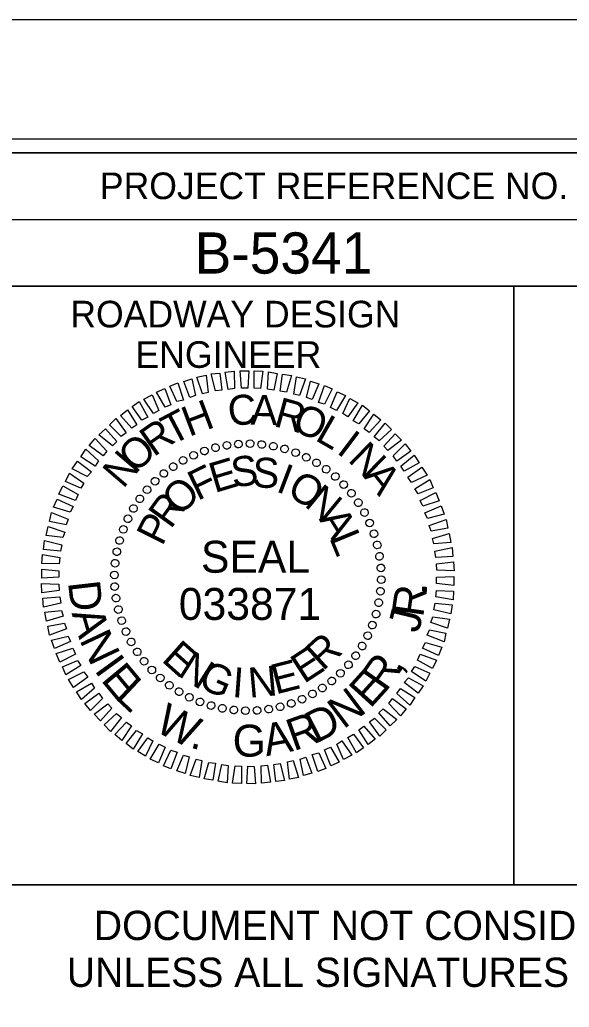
# Model space of a CAD drawing. Extents: x 572694 to 574378, y -52955 to -51855.
# Drawn here: x 574168.6 to 574271.9, y -52040.7 to -51855.1 of the extents above; entities that cross this region are included whole.
import ezdxf

# ---------------------------------------------------------------- set-up
doc = ezdxf.new("R2010")
doc.units = 0
for name, color, linetype in [('Sheet Cutting Line CELL', 7, 'Continuous'), ('Sheet Data Field CELL', 7, 'Continuous'), ('Sheet Plot Border Inside CELL', 7, 'Continuous'), ('Sheet Plot Border Outside CELL', 7, 'Continuous'), ('Sheet Professional Seal CELL', 7, 'Continuous'), ('Sheet Profile CELL', 7, 'Continuous'), ('Sheet Profile Grid Major CELL', 7, 'Continuous'), ('Sheet Sticker Exception Certification CELL', 7, 'Continuous')]:
    doc.layers.add(name, color=color, linetype=linetype)

msp = doc.modelspace()

# ---------------------------------------------------------------- linework, layer by layer
at = {"layer": 'Sheet Cutting Line CELL'}
msp.add_line((574378.5, -51855.14), (572694.5, -51855.14), dxfattribs=at)
at = {"layer": 'Sheet Plot Border Inside CELL'}
msp.add_lwpolyline([(574374, -51877.59), (572707.5, -51877.59), (572707.5, -52932.69), (574374, -52932.69)], close=True, dxfattribs=at)
at = {"layer": 'Sheet Plot Border Outside CELL'}
msp.add_lwpolyline([(574378.5, -51855.14), (572694.5, -51855.14), (572694.5, -52955.14), (574378.5, -52955.14)], close=True, dxfattribs=at)
at = {"layer": 'Sheet Professional Seal CELL'}
for p, q in [((574205.36, -51935.53), (574205.36, -51935.53)), ((574207.56, -51935.13), (574207.56, -51935.13)), ((574209.71, -51934.83), (574209.71, -51934.83)), ((574211.91, -51934.78), (574211.91, -51934.78)), ((574214.11, -51934.93), (574214.11, -51934.93)), ((574216.26, -51935.28), (574216.26, -51935.28)), ((574218.36, -51935.73), (574218.36, -51935.73)), ((574201.26, -51936.93), (574201.26, -51936.93)), ((574203.26, -51936.13), (574203.26, -51936.13)), ((574220.46, -51936.43), (574220.46, -51936.43)), ((574222.46, -51937.33), (574222.46, -51937.33)), ((574197.41, -51939.08), (574197.41, -51939.08)), ((574199.31, -51937.93), (574199.31, -51937.93)), ((574224.41, -51938.33), (574224.41, -51938.33)), ((574195.66, -51940.33), (574195.66, -51940.33)), ((574226.21, -51939.58), (574226.21, -51939.58)), ((574227.96, -51940.93), (574227.96, -51940.93)), ((574194.01, -51941.83), (574194.01, -51941.83)), ((574229.51, -51942.43), (574229.51, -51942.43)), ((574191.16, -51945.13), (574191.16, -51945.13)), ((574192.51, -51943.38), (574192.51, -51943.38)), ((574231.01, -51944.08), (574231.01, -51944.08)), ((574189.91, -51946.93), (574189.91, -51946.93)), ((574232.26, -51945.83), (574232.26, -51945.83)), ((574233.41, -51947.73), (574233.41, -51947.73)), ((574188.91, -51948.88), (574188.91, -51948.88)), ((574234.41, -51949.68), (574234.41, -51949.68)), ((574188.01, -51950.88), (574188.01, -51950.88)), ((574235.21, -51951.68), (574235.21, -51951.68)), ((574187.31, -51952.98), (574187.31, -51952.98)), ((574235.81, -51953.78), (574235.81, -51953.78)), ((574186.86, -51955.08), (574186.86, -51955.08)), ((574236.21, -51955.98), (574236.21, -51955.98)), ((574186.51, -51957.23), (574186.51, -51957.23)), ((574236.51, -51958.13), (574236.51, -51958.13)), ((574186.36, -51959.43), (574186.36, -51959.43)), ((574211.46, -51959.88), (574211.46, -51959.88)), ((574186.41, -51961.63), (574186.41, -51961.63)), ((574236.56, -51960.33), (574236.56, -51960.33)), ((574236.41, -51962.53), (574236.41, -51962.53)), ((574186.71, -51963.78), (574186.71, -51963.78)), ((574236.06, -51964.68), (574236.06, -51964.68)), ((574187.11, -51965.98), (574187.11, -51965.98)), ((574235.61, -51966.78), (574235.61, -51966.78)), ((574187.71, -51968.08), (574187.71, -51968.08)), ((574234.91, -51968.88), (574234.91, -51968.88)), ((574188.51, -51970.08), (574188.51, -51970.08)), ((574234.01, -51970.88), (574234.01, -51970.88)), ((574189.51, -51972.03), (574189.51, -51972.03)), ((574233.01, -51972.83), (574233.01, -51972.83)), ((574190.66, -51973.93), (574190.66, -51973.93)), ((574231.76, -51974.63), (574231.76, -51974.63)), ((574191.91, -51975.68), (574191.91, -51975.68)), ((574230.41, -51976.38), (574230.41, -51976.38)), ((574193.41, -51977.33), (574193.41, -51977.33)), ((574228.91, -51977.93), (574228.91, -51977.93)), ((574194.96, -51978.83), (574194.96, -51978.83)), ((574196.71, -51980.18), (574196.71, -51980.18)), ((574227.26, -51979.43), (574227.26, -51979.43)), ((574198.51, -51981.43), (574198.51, -51981.43)), ((574223.61, -51981.83), (574223.61, -51981.83)), ((574225.51, -51980.68), (574225.51, -51980.68)), ((574200.46, -51982.43), (574200.46, -51982.43)), ((574202.46, -51983.33), (574202.46, -51983.33)), ((574204.56, -51984.03), (574204.56, -51984.03)), ((574219.66, -51983.63), (574219.66, -51983.63)), ((574221.66, -51982.83), (574221.66, -51982.83)), ((574206.66, -51984.48), (574206.66, -51984.48)), ((574208.81, -51984.83), (574208.81, -51984.83)), ((574211.01, -51984.98), (574211.01, -51984.98)), ((574213.21, -51984.93), (574213.21, -51984.93)), ((574215.36, -51984.63), (574215.36, -51984.63)), ((574217.56, -51984.23), (574217.56, -51984.23))]:
    msp.add_line(p, q, dxfattribs=at)
for points in [[(574200.56, -51926.08), (574199.41, -51923.08), (574200.96, -51922.63), (574201.61, -51925.73)], [(574202.96, -51925.43), (574201.91, -51922.28), (574203.61, -51921.93), (574204.01, -51925.18)], [(574205.36, -51924.88), (574204.56, -51921.68), (574206.21, -51921.53), (574206.56, -51924.73)], [(574207.76, -51924.58), (574207.21, -51921.38), (574208.91, -51921.18), (574208.96, -51924.43)], [(574210.26, -51924.33), (574210.01, -51921.08), (574211.66, -51921.13), (574211.46, -51924.38)], [(574212.66, -51924.38), (574212.66, -51921.13), (574214.31, -51921.18), (574213.86, -51924.43)], [(574215.16, -51924.53), (574215.36, -51921.28), (574217.01, -51921.58), (574216.36, -51924.73)], [(574217.56, -51924.93), (574218.01, -51921.73), (574219.66, -51921.98), (574218.76, -51925.08)], [(574220.11, -51925.48), (574220.61, -51922.23), (574222.31, -51922.63), (574221.16, -51925.73)], [(574195.91, -51927.93), (574194.31, -51925.13), (574195.86, -51924.43), (574197.01, -51927.48)], [(574198.11, -51926.88), (574196.81, -51923.98), (574198.31, -51923.38), (574199.36, -51926.58)], [(574222.51, -51926.13), (574223.26, -51923.03), (574224.81, -51923.53), (574223.56, -51926.48)], [(574224.76, -51927.03), (574225.91, -51923.88), (574227.31, -51924.48), (574225.91, -51927.38)], [(574193.76, -51929.13), (574191.91, -51926.43), (574193.46, -51925.63), (574194.71, -51928.53)], [(574227.01, -51927.98), (574228.26, -51925.03), (574229.81, -51925.73), (574228.11, -51928.53)], [(574229.31, -51929.13), (574230.66, -51926.28), (574232.16, -51927.13), (574230.26, -51929.73)], [(574189.66, -51931.88), (574187.51, -51929.48), (574188.86, -51928.43), (574190.61, -51931.23)], [(574191.56, -51930.38), (574189.71, -51927.83), (574191.01, -51926.88), (574192.66, -51929.78)], [(574231.26, -51930.48), (574233.01, -51927.58), (574234.31, -51928.63), (574232.36, -51931.08)], [(574187.66, -51933.43), (574185.46, -51931.23), (574186.66, -51930.03), (574188.61, -51932.73)], [(574233.31, -51931.98), (574235.16, -51929.23), (574236.46, -51930.33), (574234.26, -51932.68)], [(574186.01, -51935.18), (574183.46, -51933.13), (574184.71, -51931.98), (574186.81, -51934.38)], [(574235.21, -51933.53), (574237.26, -51930.93), (574238.46, -51932.13), (574236.16, -51934.28)], [(574184.26, -51937.08), (574181.66, -51935.13), (574182.76, -51933.83), (574184.96, -51936.18)], [(574237.01, -51935.28), (574239.16, -51932.93), (574240.36, -51934.13), (574237.76, -51936.08)], [(574182.76, -51938.98), (574180.06, -51937.28), (574181.01, -51935.83), (574183.41, -51938.03)], [(574238.76, -51937.08), (574241.06, -51934.83), (574242.11, -51936.18), (574239.46, -51938.08)], [(574240.26, -51939.03), (574242.71, -51936.93), (574243.66, -51938.38), (574240.86, -51939.98)], [(574181.26, -51940.98), (574178.46, -51939.48), (574179.46, -51938.08), (574182.06, -51940.08)], [(574241.56, -51941.08), (574244.21, -51939.18), (574245.16, -51940.68), (574242.26, -51942.08)], [(574180.06, -51943.13), (574177.21, -51941.88), (574177.96, -51940.33), (574180.66, -51942.18)], [(574179.06, -51945.43), (574175.96, -51944.28), (574176.71, -51942.73), (574179.56, -51944.33)], [(574242.86, -51943.28), (574245.66, -51941.53), (574246.31, -51943.08), (574243.46, -51944.23)], [(574243.86, -51945.43), (574246.81, -51943.93), (574247.46, -51945.53), (574244.36, -51946.53)], [(574178.06, -51947.63), (574174.96, -51946.73), (574175.61, -51945.18), (574178.61, -51946.58)], [(574244.76, -51947.78), (574247.81, -51946.48), (574248.36, -51948.03), (574245.26, -51948.83)], [(574177.31, -51950.03), (574174.21, -51949.38), (574174.56, -51947.73), (574177.71, -51948.98)], [(574176.66, -51952.43), (574173.56, -51952.03), (574173.91, -51950.33), (574177.06, -51951.38)], [(574245.56, -51950.18), (574248.76, -51949.03), (574249.06, -51950.68), (574245.91, -51951.23)], [(574246.16, -51952.58), (574249.31, -51951.63), (574249.61, -51953.33), (574246.46, -51953.63)], [(574176.26, -51954.98), (574173.06, -51954.68), (574173.26, -51952.98), (574176.51, -51953.78)], [(574246.61, -51954.98), (574249.86, -51954.28), (574250.01, -51955.98), (574246.81, -51956.18)], [(574176.01, -51957.38), (574172.76, -51957.28), (574172.86, -51955.63), (574176.11, -51956.18)], [(574246.91, -51957.38), (574250.16, -51956.98), (574250.26, -51958.68), (574247.01, -51958.58)], [(574175.96, -51959.88), (574172.71, -51960.03), (574172.71, -51958.33), (574175.96, -51958.68)], [(574246.96, -51959.88), (574250.21, -51959.73), (574250.21, -51961.43), (574246.96, -51961.08)], [(574176.01, -51962.38), (574172.76, -51962.78), (574172.66, -51961.08), (574175.91, -51961.18)], [(574176.31, -51964.78), (574173.06, -51965.48), (574172.91, -51963.78), (574176.11, -51963.58)], [(574246.91, -51962.38), (574250.16, -51962.48), (574250.06, -51964.13), (574246.81, -51963.58)], [(574246.66, -51964.78), (574249.86, -51965.08), (574249.66, -51966.78), (574246.41, -51965.98)], [(574176.76, -51967.18), (574173.61, -51968.13), (574173.31, -51966.43), (574176.46, -51966.13)], [(574246.26, -51967.33), (574249.36, -51967.73), (574249.01, -51969.43), (574245.86, -51968.38)], [(574177.36, -51969.58), (574174.16, -51970.73), (574173.86, -51969.08), (574177.01, -51968.53)], [(574178.16, -51971.98), (574175.11, -51973.28), (574174.56, -51971.73), (574177.66, -51970.93)], [(574245.61, -51969.73), (574248.71, -51970.38), (574248.36, -51972.03), (574245.21, -51970.78)], [(574244.86, -51972.13), (574247.96, -51973.03), (574247.31, -51974.58), (574244.31, -51973.18)], [(574179.06, -51974.33), (574176.11, -51975.83), (574175.46, -51974.23), (574178.56, -51973.23)], [(574243.86, -51974.33), (574246.96, -51975.48), (574246.21, -51977.03), (574243.36, -51975.43)], [(574180.06, -51976.48), (574177.26, -51978.23), (574176.61, -51976.68), (574179.46, -51975.53)], [(574242.86, -51976.63), (574245.71, -51977.88), (574244.96, -51979.43), (574242.26, -51977.58)], [(574181.36, -51978.68), (574178.71, -51980.58), (574177.76, -51979.08), (574180.66, -51977.68)], [(574182.66, -51980.73), (574180.21, -51982.83), (574179.26, -51981.38), (574182.06, -51979.78)], [(574241.66, -51978.78), (574244.46, -51980.28), (574243.46, -51981.68), (574240.86, -51979.68)], [(574184.16, -51982.68), (574181.86, -51984.93), (574180.81, -51983.58), (574183.46, -51981.68)], [(574240.16, -51980.78), (574242.86, -51982.48), (574241.91, -51983.93), (574239.51, -51981.73)], [(574185.91, -51984.48), (574183.76, -51986.83), (574182.56, -51985.63), (574185.16, -51983.68)], [(574238.66, -51982.68), (574241.26, -51984.63), (574240.16, -51985.93), (574237.96, -51983.58)], [(574187.71, -51986.23), (574185.66, -51988.83), (574184.46, -51987.63), (574186.76, -51985.48)], [(574236.91, -51984.58), (574239.46, -51986.63), (574238.21, -51987.78), (574236.11, -51985.38)], [(574189.61, -51987.78), (574187.76, -51990.53), (574186.46, -51989.43), (574188.66, -51987.08)], [(574235.26, -51986.33), (574237.46, -51988.53), (574236.26, -51989.73), (574234.31, -51987.03)], [(574191.66, -51989.28), (574189.91, -51992.18), (574188.61, -51991.13), (574190.56, -51988.68)], [(574231.36, -51989.38), (574233.21, -51991.93), (574231.91, -51992.88), (574230.26, -51989.98)], [(574233.26, -51987.88), (574235.41, -51990.28), (574234.06, -51991.33), (574232.31, -51988.53)], [(574193.61, -51990.63), (574192.26, -51993.48), (574190.76, -51992.63), (574192.66, -51990.03)], [(574195.91, -51991.78), (574194.66, -51994.73), (574193.11, -51994.03), (574194.81, -51991.23)], [(574229.16, -51990.63), (574231.01, -51993.33), (574229.46, -51994.13), (574228.21, -51991.23)], [(574198.16, -51992.73), (574197.01, -51995.88), (574195.61, -51995.28), (574197.01, -51992.38)], [(574200.41, -51993.63), (574199.66, -51996.73), (574198.11, -51996.23), (574199.36, -51993.28)], [(574224.81, -51992.88), (574226.11, -51995.78), (574224.61, -51996.38), (574223.56, -51993.18)], [(574227.01, -51991.83), (574228.61, -51994.63), (574227.06, -51995.33), (574225.91, -51992.28)], [(574202.81, -51994.28), (574202.31, -51997.53), (574200.61, -51997.13), (574201.76, -51994.03)], [(574205.36, -51994.83), (574204.91, -51998.03), (574203.26, -51997.78), (574204.16, -51994.68)], [(574207.76, -51995.23), (574207.56, -51998.48), (574205.91, -51998.18), (574206.56, -51995.03)], [(574215.16, -51995.18), (574215.71, -51998.38), (574214.01, -51998.58), (574213.96, -51995.33)], [(574217.56, -51994.88), (574218.36, -51998.08), (574216.71, -51998.23), (574216.36, -51995.03)], [(574219.96, -51994.33), (574221.01, -51997.48), (574219.31, -51997.83), (574218.91, -51994.58)], [(574222.36, -51993.68), (574223.51, -51996.68), (574221.96, -51997.13), (574221.31, -51994.03)], [(574210.26, -51995.38), (574210.26, -51998.63), (574208.61, -51998.58), (574209.06, -51995.33)], [(574212.66, -51995.43), (574212.91, -51998.68), (574211.26, -51998.63), (574211.46, -51995.38)]]:
    msp.add_lwpolyline(points, close=True, dxfattribs=at)
for centre, major_axis in [((574203.3, -51936.17), (-0.234, 0.681)), ((574205.39, -51935.54), (-0.174, 0.699)), ((574207.54, -51935.11), (-0.113, 0.711)), ((574209.71, -51934.86), (-0.05, 0.718)), ((574211.9, -51934.8), (0.013, 0.72)), ((574214.08, -51934.94), (0.075, 0.716)), ((574216.25, -51935.26), (0.137, 0.707)), ((574218.37, -51935.77), (0.198, 0.692)), ((574220.45, -51936.47), (0.258, 0.672)), ((574199.3, -51937.94), (-0.349, 0.63)), ((574201.26, -51936.97), (-0.293, 0.658)), ((574222.46, -51937.34), (0.316, 0.647)), ((574224.38, -51938.38), (0.371, 0.617)), ((574195.68, -51940.39), (-0.453, 0.56)), ((574197.44, -51939.09), (-0.403, 0.597)), ((574226.2, -51939.59), (0.423, 0.582)), ((574194.04, -51941.84), (-0.5, 0.518)), ((574227.92, -51940.95), (0.472, 0.543)), ((574192.53, -51943.43), (-0.543, 0.472)), ((574229.5, -51942.46), (0.518, 0.5)), ((574230.95, -51944.1), (0.56, 0.453)), ((574191.17, -51945.14), (-0.582, 0.423)), ((574232.25, -51945.85), (0.597, 0.403)), ((574189.96, -51946.96), (-0.617, 0.371)), ((574233.4, -51947.72), (0.63, 0.349)), ((574188.92, -51948.89), (-0.647, 0.316)), ((574188.05, -51950.89), (-0.672, 0.258)), ((574234.37, -51949.68), (0.658, 0.293)), ((574187.35, -51952.97), (-0.692, 0.198)), ((574235.18, -51951.71), (0.681, 0.234)), ((574186.84, -51955.09), (-0.707, 0.137)), ((574235.8, -51953.81), (0.699, 0.174)), ((574236.23, -51955.96), (0.711, 0.113)), ((574186.52, -51957.26), (-0.716, 0.075)), ((574236.48, -51958.13), (0.718, 0.05)), ((574186.39, -51959.44), (-0.72, 0.013)), ((574236.54, -51960.32), (0.72, -0.013)), ((574186.44, -51961.63), (-0.718, -0.05)), ((574236.4, -51962.5), (0.716, -0.075)), ((574186.69, -51963.8), (-0.711, -0.113)), ((574187.13, -51965.95), (-0.699, -0.174)), ((574236.08, -51964.66), (0.707, -0.137)), ((574187.75, -51968.04), (-0.681, -0.234)), ((574235.57, -51966.79), (0.692, -0.198)), ((574188.55, -51970.08), (-0.658, -0.293)), ((574234.88, -51968.87), (0.672, -0.258)), ((574234, -51970.87), (0.647, -0.316)), ((574189.53, -51972.04), (-0.63, -0.349)), ((574232.96, -51972.8), (0.617, -0.371)), ((574190.67, -51973.9), (-0.597, -0.403)), ((574231.75, -51974.62), (0.582, -0.423)), ((574191.97, -51975.66), (-0.56, -0.453)), ((574193.42, -51977.3), (-0.518, -0.5)), ((574230.39, -51976.33), (0.543, -0.472)), ((574195.01, -51978.81), (-0.472, -0.543)), ((574228.88, -51977.92), (0.5, -0.518)), ((574196.72, -51980.17), (-0.423, -0.582)), ((574225.49, -51980.67), (0.403, -0.597)), ((574227.25, -51979.37), (0.453, -0.56)), ((574198.54, -51981.38), (-0.371, -0.617)), ((574200.47, -51982.42), (-0.316, -0.647)), ((574221.66, -51982.79), (0.293, -0.658)), ((574223.62, -51981.81), (0.349, -0.63)), ((574202.47, -51983.29), (-0.258, -0.672)), ((574204.55, -51983.99), (-0.198, -0.692)), ((574206.68, -51984.5), (-0.137, -0.707)), ((574208.84, -51984.82), (-0.075, -0.716)), ((574215.39, -51984.65), (0.113, -0.711)), ((574217.53, -51984.21), (0.174, -0.699)), ((574219.63, -51983.59), (0.234, -0.681)), ((574211.02, -51984.96), (-0.013, -0.72)), ((574213.21, -51984.9), (0.05, -0.718))]:
    msp.add_ellipse(centre, major_axis=major_axis, ratio=0.999708, dxfattribs=at)
at = {"layer": 'Sheet Profile CELL'}
for p, q in [((574161.45, -51892.69), (574361.5, -51892.69)), ((574261.5, -51905.19), (574261.5, -52017.64))]:
    msp.add_line(p, q, dxfattribs=at)
for points in [[(574361.5, -51880.14), (572861.5, -51880.14), (572861.5, -52930.14), (574361.5, -52930.14)], [(574161.45, -51880.14), (574361.5, -51880.14), (574361.5, -51905.19), (574161.45, -51905.19)], [(574161.45, -51905.19), (574261.5, -51905.19), (574261.5, -52017.69), (574161.45, -52017.69)], [(574261.5, -51905.19), (574361.5, -51905.19), (574361.5, -52017.69), (574261.5, -52017.69)]]:
    msp.add_lwpolyline(points, close=True, dxfattribs=at)
at = {"layer": 'Sheet Profile Grid Major CELL'}
msp.add_lwpolyline([(573961.5, -51880.14), (574011.5, -51880.14), (574011.5, -52905.14), (574061.5, -52905.14), (574061.5, -51880.14), (574111.5, -51880.14), (574111.5, -52905.14), (574161.5, -52905.14), (574161.5, -51880.14), (574187.8, -51880.14)], dxfattribs=at)
at = {"layer": 'Sheet Sticker Exception Certification CELL'}
msp.add_line((574161.45, -52017.69), (574361.48, -52017.69), dxfattribs=at)

# ---------------------------------------------------------------- texts
at = {"layer": 'Sheet Data Field CELL'}
msp.add_text(' B-5341  ', height=7.75, dxfattribs=at).set_placement((574198.58, -51902.84))
at = {"layer": 'Sheet Professional Seal CELL'}
for s, height, rotation, p in [('H', 5.64, 20.6195, (574200.41, -51933.53)), ('C', 5.64, 6.2199, (574208.01, -51931.53)), ('A', 5.64, 359.0203, (574211.96, -51931.23)), ('R', 5.64, 344.6211, (574216.16, -51931.43)), ('T', 5.64, 27.8198, (574197.16, -51935.18)), ('O', 5.64, 337.4212, (574219.51, -51932.18)), ('L', 5.64, 330.2209, (574223.91, -51934.03)), ('R', 5.64, 35.0205, (574193.76, -51937.38)), ('O', 5.64, 42.2217, (574190.31, -51940.48)), ('I', 5.64, 323.0201, (574227.96, -51936.43)), ('N', 5.64, 315.8189, (574230.11, -51937.98)), ('N', 5.64, 49.4235, (574188.01, -51943.38)), ('E', 5.64, 16.6111, (574205.21, -51944.08)), ('S', 5.64, 7.2556, (574208.66, -51943.03)), ('S', 5.64, 357.9004, (574212.26, -51942.98)), ('F', 5.64, 25.967, (574202.01, -51945.58)), ('I', 5.64, 339.1896, (574216.56, -51943.68)), ('A', 5.64, 308.6172, (574233.06, -51940.93)), ('O', 5.64, 329.8335, (574218.56, -51944.38)), ('O', 5.64, 44.6812, (574198.71, -51948.53)), ('N', 5.64, 320.4766, (574221.91, -51946.38)), ('R', 5.64, 54.0397, (574196.96, -51950.98)), ('P', 5.64, 63.3989, (574195.36, -51954.18)), ('A', 5.64, 301.7603, (574224.76, -51948.98)), ('L', 5.64, 292.4008, (574226.71, -51952.43)), ('SEAL', 5.998, 360, (574202.66, -51959.03)), ('D', 6, 276.5178, (574177.65, -51960.82)), ('R', 6, 81.8439, (574244.41, -51967.54)), ('.', 6, 89.3242, (574245.13, -51963.18)), ('A', 6, 286.3936, (574178.31, -51966.6)), ('J', 6, 76.5861, (574243.57, -51970.52)), ('N', 6, 295.2339, (574179.74, -51971.62)), ('R', 5.64, 42.4814, (574225.56, -51977.63)), ('E', 5.64, 318.2769, (574195.06, -51975.53)), ('E', 5.64, 33.1241, (574222.01, -51979.98)), ('I', 6, 305.9598, (574182.48, -51977.32)), ('N', 5.64, 327.634, (574198.06, -51978.23)), ('R', 6, 54.8717, (574237.35, -51981.65)), ('E', 6, 309.7617, (574183.7, -51979.2)), ('G', 5.64, 336.9902, (574201.86, -51980.48)), ('N', 5.64, 5.0564, (574211.76, -51982.53)), ('E', 5.64, 14.4118, (574216.71, -51981.93)), (',', 6, 62.352, (574239.97, -51978.09)), ('I', 5.64, 355.7012, (574208.41, -51982.38)), ('E', 6, 47.7624, (574234.46, -51984.68)), ('L', 6, 316.871, (574186.3, -51982.49)), ('N', 6, 37.0366, (574229.44, -51988.53)), ('W', 6, 333.3462, (574193.75, -51988.7)), ('D', 6, 27.1608, (574224.26, -51991.19)), ('R', 6, 19.6805, (574220.08, -51992.59)), ('G', 6, 0.1144, (574208.62, -51993.59)), ('A', 6, 10.8402, (574214.95, -51993.52)), ('.', 6, 345.8802, (574200.42, -51991.85))]:
    msp.add_text(s, height=height, rotation=rotation, dxfattribs=at).set_placement(p)
msp.add_text('033871', height=5.998, dxfattribs=at).set_placement((574198.49, -51967.89))
at = {"layer": 'Sheet Profile CELL'}
for s, height, p in [('PROJECT REFERENCE NO.', 5.0001, (574183.65, -51888.84)), ('ROADWAY DESIGN', 5.0001, (574178.1, -51912.94)), ('ENGINEER', 5, (574190.35, -51920.54))]:
    msp.add_text(s, height=height, dxfattribs=at).set_placement(p)
at = {"layer": 'Sheet Sticker Exception Certification CELL'}
for s, p in [('DOCUMENT NOT CONSIDERED FINAL', (574182.52, -52028.04)), ('UNLESS ALL SIGNATURES COMPLETED', (574177.44, -52036.84))]:
    msp.add_text(s, height=5.5, dxfattribs=at).set_placement(p)

doc.saveas('drawing.dxf')
